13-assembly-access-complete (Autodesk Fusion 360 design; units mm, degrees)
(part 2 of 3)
sketch "B Facet 180 Triangle 3" plane through (0, -75, 0) normal (0, -1, 0) x axis (-1, 0, 0)
  line L1 (60.9665, 27.066) -> (-2.067, -27.066)
  line L2 (124, -27.066) -> (60.9665, 27.066)
  line L3 (-2.067, -27.066) -> (124, -27.066)
  line L4 (60.9665, 21.7934) -> (8.7304, -23.066)
  line L5 (113.2026, -23.066) -> (60.9665, 21.7934)
  line L6 (8.7304, -23.066) -> (113.2026, -23.066)
  point P1 (0, 0)
  point P2 (-2.067, -27.066)
  point P3 (60.9665, 27.066)
  point P4 (124, -27.066)
  dimension "d477" distance P1 P2 = 2.067 (= "Linear Dimension-2")
  dimension "d478" distance P1 P2 = 27.066 (= "Linear Dimension-3")
  dimension "d479" distance P1 P3 = 60.9665 (= "Linear Dimension-4")
  dimension "d480" distance P1 P3 = 27.066 (= "Linear Dimension-5")
  dimension "d481" distance P1 P4 = 124 (= "Linear Dimension-6")
  dimension "d482" distance P1 P4 = 27.066 (= "Linear Dimension-7")
  dimension "d483" = 4 (= "memberWidth / 2")
extrude "Extrude14" cut sketch "B Facet 180 Triangle 3" profile of L5 L6 L4 against normal blind 4.7 (magnitude of "-( wall + 0.2 mm )")
sketch "B Facet 180 Triangle 4" plane through (0, -75, 0) normal (0, -1, 0) x axis (-1, 0, 0)
  line L1 (124, -27.066) -> (60.9665, 27.066)
  line L2 (124, 27.066) -> (124, -27.066)
  line L3 (60.9665, 27.066) -> (124, 27.066)
  line L4 (120, -18.3583) -> (71.7639, 23.066)
  line L5 (120, 23.066) -> (120, -18.3583)
  line L6 (71.7639, 23.066) -> (120, 23.066)
  point P1 (0, 0)
  point P2 (60.9665, 27.066)
  point P3 (124, -27.066)
  point P4 (124, 27.066)
  dimension "d486" distance P1 P2 = 60.9665 (= "Linear Dimension-2")
  dimension "d487" distance P1 P2 = 27.066 (= "Linear Dimension-3")
  dimension "d488" distance P1 P3 = 124 (= "Linear Dimension-4")
  dimension "d489" distance P1 P3 = 27.066 (= "Linear Dimension-5")
  dimension "d490" distance P1 P4 = 124 (= "Linear Dimension-6")
  dimension "d491" distance P1 P4 = 27.066 (= "Linear Dimension-7")
  dimension "d492" = -4 (= "-memberWidth / 2")
extrude "Extrude15" cut sketch "B Facet 180 Triangle 4" profile of L5 L6 L4 against normal blind 4.7 (magnitude of "-( wall + 0.2 mm )")
fillet "Fillet5" radius 1.5 (= "apertureRadius")
work_plane "WorkPlane11" RotateAngle 135 ExtraOffset 0
work_plane "WorkPlane12" AlongDistance 75 (= "bodyWidth / 2") ExtraOffset 0
sketch "B Facet 225 Triangle 1" plane through (0, -53.033, -53.033) normal (0, -0.7071, -0.7071) x axis (1, 0, 0)
  line L1 (23.9949, -27.066) -> (62.2721, 27.066)
  line L2 (0.1814, 27.066) -> (23.9949, -27.066)
  line L3 (62.2721, 27.066) -> (0.1814, 27.066)
  line L4 (24.81, -18.9852) -> (54.5447, 23.066)
  line L5 (6.311, 23.066) -> (24.81, -18.9852)
  line L6 (54.5447, 23.066) -> (6.311, 23.066)
  point P1 (0, 0)
  point P2 (62.2721, 27.066)
  point P3 (23.9949, -27.066)
  point P4 (0.1814, 27.066)
  dimension "d501" distance P1 P2 = 62.2721 (= "Linear Dimension-2")
  dimension "d502" distance P1 P2 = 27.066 (= "Linear Dimension-3")
  dimension "d503" distance P1 P3 = 23.9949 (= "Linear Dimension-4")
  dimension "d504" distance P1 P3 = 27.066 (= "Linear Dimension-5")
  dimension "d505" distance P1 P4 = 0.1814 (= "Linear Dimension-6")
  dimension "d506" distance P1 P4 = 27.066 (= "Linear Dimension-7")
  dimension "d507" = 4 (= "memberWidth / 2")
extrude "Extrude16" cut sketch "B Facet 225 Triangle 1" profile of L5 L6 L4 against normal blind 4.7 (magnitude of "-( wall + 0.2 mm )")
sketch "B Facet 225 Triangle 2" plane through (0, -53.033, -53.033) normal (0, -0.7071, -0.7071) x axis (1, 0, 0)
  line L1 (0.1814, 27.066) -> (23.9949, -27.066)
  line L2 (-74.6684, -27.066) -> (0.1814, 27.066)
  line L3 (23.9949, -27.066) -> (-74.6684, -27.066)
  line L4 (-1.4863, 20.9235) -> (17.8653, -23.066)
  line L5 (-62.3117, -23.066) -> (-1.4863, 20.9235)
  line L6 (17.8653, -23.066) -> (-62.3117, -23.066)
  point P1 (0, 0)
  point P2 (23.9949, -27.066)
  point P3 (0.1814, 27.066)
  point P4 (-74.6684, -27.066)
  dimension "d510" distance P1 P2 = 23.9949 (= "Linear Dimension-2")
  dimension "d511" distance P1 P2 = 27.066 (= "Linear Dimension-3")
  dimension "d512" distance P1 P3 = 0.1814 (= "Linear Dimension-4")
  dimension "d513" distance P1 P3 = 27.066 (= "Linear Dimension-5")
  dimension "d514" distance P1 P4 = 74.6684 (= "Linear Dimension-6")
  dimension "d515" distance P1 P4 = 27.066 (= "Linear Dimension-7")
  dimension "d516" = -4 (= "-memberWidth / 2")
extrude "Extrude17" cut sketch "B Facet 225 Triangle 2" profile of L5 L6 L4 against normal blind 4.7 (magnitude of "-( wall + 0.2 mm )")
sketch "B Facet 225 Triangle 3" plane through (0, -53.033, -53.033) normal (0, -0.7071, -0.7071) x axis (1, 0, 0)
  line L1 (-74.6684, -27.066) -> (0.1814, 27.066)
  line L2 (-124, 27.066) -> (-74.6684, -27.066)
  line L3 (0.1814, 27.066) -> (-124, 27.066)
  line L4 (-74.1179, -21.7315) -> (-12.1753, 23.066)
  line L5 (-114.9429, 23.066) -> (-74.1179, -21.7315)
  line L6 (-12.1753, 23.066) -> (-114.9429, 23.066)
  point P1 (0, 0)
  point P2 (0.1814, 27.066)
  point P3 (-74.6684, -27.066)
  point P4 (-124, 27.066)
  dimension "d519" distance P1 P2 = 0.1814 (= "Linear Dimension-2")
  dimension "d520" distance P1 P2 = 27.066 (= "Linear Dimension-3")
  dimension "d521" distance P1 P3 = 74.6684 (= "Linear Dimension-4")
  dimension "d522" distance P1 P3 = 27.066 (= "Linear Dimension-5")
  dimension "d523" distance P1 P4 = 124 (= "Linear Dimension-6")
  dimension "d524" distance P1 P4 = 27.066 (= "Linear Dimension-7")
  dimension "d525" = 4 (= "memberWidth / 2")
extrude "Extrude18" cut sketch "B Facet 225 Triangle 3" profile of L5 L6 L4 against normal blind 4.7 (magnitude of "-( wall + 0.2 mm )")
sketch "B Facet 225 Triangle 4" plane through (0, -53.033, -53.033) normal (0, -0.7071, -0.7071) x axis (1, 0, 0)
  line L1 (-124, 27.066) -> (-74.6684, -27.066)
  line L2 (-124, -27.066) -> (-124, 27.066)
  line L3 (-74.6684, -27.066) -> (-124, -27.066)
  line L4 (-120, 16.7383) -> (-83.7255, -23.066)
  line L5 (-120, -23.066) -> (-120, 16.7383)
  line L6 (-83.7255, -23.066) -> (-120, -23.066)
  point P1 (0, 0)
  point P2 (-74.6684, -27.066)
  point P3 (-124, 27.066)
  point P4 (-124, -27.066)
  dimension "d528" distance P1 P2 = 74.6684 (= "Linear Dimension-2")
  dimension "d529" distance P1 P2 = 27.066 (= "Linear Dimension-3")
  dimension "d530" distance P1 P3 = 124 (= "Linear Dimension-4")
  dimension "d531" distance P1 P3 = 27.066 (= "Linear Dimension-5")
  dimension "d532" distance P1 P4 = 124 (= "Linear Dimension-6")
  dimension "d533" distance P1 P4 = 27.066 (= "Linear Dimension-7")
  dimension "d534" = -4 (= "-memberWidth / 2")
extrude "Extrude19" cut sketch "B Facet 225 Triangle 4" profile of L5 L6 L4 against normal blind 4.7 (magnitude of "-( wall + 0.2 mm )")
fillet "Fillet6" radius 1.5 (= "apertureRadius")
work_plane "WorkPlane13" RotateAngle 180 ExtraOffset 0
work_plane "WorkPlane14" AlongDistance 75 (= "bodyWidth / 2") ExtraOffset 0
sketch "B Facet 270 Triangle 1" plane through (0, 0, -75) normal (0, 0, -1) x axis (-1, 0, 0)
  line L1 (36.9655, 27.066) -> (-17.1665, -27.066)
  line L2 (53.4167, -27.066) -> (36.9655, 27.066)
  line L3 (-17.1665, -27.066) -> (53.4167, -27.066)
  line L4 (35.0777, 19.5214) -> (-7.5097, -23.066)
  line L5 (48.0205, -23.066) -> (35.0777, 19.5214)
  line L6 (-7.5097, -23.066) -> (48.0205, -23.066)
  point P1 (0, 0)
  point P2 (-17.1665, -27.066)
  point P3 (36.9655, 27.066)
  point P4 (53.4167, -27.066)
  dimension "d543" distance P1 P2 = 17.1665 (= "Linear Dimension-2")
  dimension "d544" distance P1 P2 = 27.066 (= "Linear Dimension-3")
  dimension "d545" distance P1 P3 = 36.9655 (= "Linear Dimension-4")
  dimension "d546" distance P1 P3 = 27.066 (= "Linear Dimension-5")
  dimension "d547" distance P1 P4 = 53.4167 (= "Linear Dimension-6")
  dimension "d548" distance P1 P4 = 27.066 (= "Linear Dimension-7")
  dimension "d549" = 4 (= "memberWidth / 2")
extrude "Extrude20" cut sketch "B Facet 270 Triangle 1" profile of L5 L6 L4 against normal blind 4.7 (magnitude of "-( wall + 0.2 mm )")
sketch "B Facet 270 Triangle 2" plane through (0, 0, -75) normal (0, 0, -1) x axis (-1, 0, 0)
  line L1 (53.4167, -27.066) -> (36.9655, 27.066)
  line L2 (124, 27.066) -> (53.4167, -27.066)
  line L3 (36.9655, 27.066) -> (124, 27.066)
  line L4 (55.5648, -20.3777) -> (42.3618, 23.066)
  line L5 (112.2115, 23.066) -> (55.5648, -20.3777)
  line L6 (42.3618, 23.066) -> (112.2115, 23.066)
  point P1 (0, 0)
  point P2 (36.9655, 27.066)
  point P3 (53.4167, -27.066)
  point P4 (124, 27.066)
  dimension "d552" distance P1 P2 = 36.9655 (= "Linear Dimension-2")
  dimension "d553" distance P1 P2 = 27.066 (= "Linear Dimension-3")
  dimension "d554" distance P1 P3 = 53.4167 (= "Linear Dimension-4")
  dimension "d555" distance P1 P3 = 27.066 (= "Linear Dimension-5")
  dimension "d556" distance P1 P4 = 124 (= "Linear Dimension-6")
  dimension "d557" distance P1 P4 = 27.066 (= "Linear Dimension-7")
  dimension "d558" = -4 (= "-memberWidth / 2")
extrude "Extrude21" cut sketch "B Facet 270 Triangle 2" profile of L5 L6 L4 against normal blind 4.7 (magnitude of "-( wall + 0.2 mm )")
sketch "B Facet 270 Triangle 3" plane through (0, 0, -75) normal (0, 0, -1) x axis (-1, 0, 0)
  line L1 (124, 27.066) -> (53.4167, -27.066)
  line L2 (124, -27.066) -> (124, 27.066)
  line L3 (53.4167, -27.066) -> (124, -27.066)
  line L4 (120, 18.9574) -> (65.2053, -23.066)
  line L5 (120, -23.066) -> (120, 18.9574)
  line L6 (65.2053, -23.066) -> (120, -23.066)
  point P1 (0, 0)
  point P2 (53.4167, -27.066)
  point P3 (124, 27.066)
  point P4 (124, -27.066)
  dimension "d561" distance P1 P2 = 53.4167 (= "Linear Dimension-2")
  dimension "d562" distance P1 P2 = 27.066 (= "Linear Dimension-3")
  dimension "d563" distance P1 P3 = 124 (= "Linear Dimension-4")
  dimension "d564" distance P1 P3 = 27.066 (= "Linear Dimension-5")
  dimension "d565" distance P1 P4 = 124 (= "Linear Dimension-6")
  dimension "d566" distance P1 P4 = 27.066 (= "Linear Dimension-7")
  dimension "d567" = 4 (= "memberWidth / 2")
extrude "Extrude22" cut sketch "B Facet 270 Triangle 3" profile of L5 L6 L4 against normal blind 4.7 (magnitude of "-( wall + 0.2 mm )")
fillet "Fillet7" radius 1.5 (= "apertureRadius")
work_plane "WorkPlane15" RotateAngle 225 ExtraOffset 0
work_plane "WorkPlane16" AlongDistance 75 (= "bodyWidth / 2") ExtraOffset 0
sketch "B Facet 315 Triangle 1" plane through (0, 53.033, -53.033) normal (0, 0.7071, -0.7071) x axis (1, 0, 0)
  line L1 (-82.0711, -27.066) -> (-43.7939, 27.066)
  line L2 (-124, 27.066) -> (-82.0711, -27.066)
  line L3 (-43.7939, 27.066) -> (-124, 27.066)
  line L4 (-82.2175, -20.3449) -> (-51.5213, 23.066)
  line L5 (-115.8422, 23.066) -> (-82.2175, -20.3449)
  line L6 (-51.5213, 23.066) -> (-115.8422, 23.066)
  point P1 (0, 0)
  point P2 (-43.7939, 27.066)
  point P3 (-82.0711, -27.066)
  point P4 (-124, 27.066)
  dimension "d576" distance P1 P2 = 43.7939 (= "Linear Dimension-2")
  dimension "d577" distance P1 P2 = 27.066 (= "Linear Dimension-3")
  dimension "d578" distance P1 P3 = 82.0711 (= "Linear Dimension-4")
  dimension "d579" distance P1 P3 = 27.066 (= "Linear Dimension-5")
  dimension "d580" distance P1 P4 = 124 (= "Linear Dimension-6")
  dimension "d581" distance P1 P4 = 27.066 (= "Linear Dimension-7")
  dimension "d582" = 4 (= "memberWidth / 2")
extrude "Extrude23" cut sketch "B Facet 315 Triangle 1" profile of L5 L6 L4 against normal blind 4.7 (magnitude of "-( wall + 0.2 mm )")
sketch "B Facet 315 Triangle 2" plane through (0, 53.033, -53.033) normal (0, 0.7071, -0.7071) x axis (1, 0, 0)
  line L1 (-124, 27.066) -> (-82.0711, -27.066)
  line L2 (-124, -27.066) -> (-124, 27.066)
  line L3 (-82.0711, -27.066) -> (-124, -27.066)
  line L4 (-120, 15.3697) -> (-90.2289, -23.066)
  line L5 (-120, -23.066) -> (-120, 15.3697)
  line L6 (-90.2289, -23.066) -> (-120, -23.066)
  point P1 (0, 0)
  point P2 (-82.0711, -27.066)
  point P3 (-124, 27.066)
  point P4 (-124, -27.066)
  dimension "d585" distance P1 P2 = 82.0711 (= "Linear Dimension-2")
  dimension "d586" distance P1 P2 = 27.066 (= "Linear Dimension-3")
  dimension "d587" distance P1 P3 = 124 (= "Linear Dimension-4")
  dimension "d588" distance P1 P3 = 27.066 (= "Linear Dimension-5")
  dimension "d589" distance P1 P4 = 124 (= "Linear Dimension-6")
  dimension "d590" distance P1 P4 = 27.066 (= "Linear Dimension-7")
  dimension "d591" = -4 (= "-memberWidth / 2")
extrude "Extrude24" cut sketch "B Facet 315 Triangle 2" profile of L5 L6 L4 against normal blind 4.7 (magnitude of "-( wall + 0.2 mm )")
fillet "Fillet8" radius 1.5 (= "apertureRadius")
work_plane "WorkPlane17" AlongDistance 0.5 (= "qFront") ExtraOffset 0
sketch "A Central Carrier sketch" plane through (0.3536, 0.3536, 0) normal (0.7071, 0.7071, 0) x axis (0, 0, 1)
  circle C1 centre (0, 0) radius 26
  dimension "d598" diameter C1 = 52 (= "carrierOD")
extrude "Extrude25" new body sketch "A Central Carrier sketch" along normal blind 18 (= "spokeDepth")
work_plane "WorkPlane18" AlongDistance 0.5 (= "qFront") ExtraOffset 0
sketch "A Spoke 1 Profile" plane through (0.3536, 0.3536, 0) normal (0.7071, 0.7071, 0) x axis (0, 0, 1)
  line L1 (37.3643, -145.3579) -> (-4.7984, -1.4054)
  line L2 (46.9611, -142.547) -> (37.3643, -145.3579)
  line L3 (4.7984, 1.4054) -> (46.9611, -142.547)
  line L4 (-4.7984, -1.4054) -> (4.7984, 1.4054)
  point P1 (0, 0)
  point P2 (-4.7984, -1.4054)
  point P3 (37.3643, -145.3579)
  point P4 (46.9611, -142.547)
  point P5 (4.7984, 1.4054)
  dimension "d603" distance P1 P2 = 4.7984 (= "Linear Dimension-2")
  dimension "d604" distance P1 P2 = 1.4054 (= "Linear Dimension-3")
  dimension "d605" distance P1 P3 = 37.3643 (= "Linear Dimension-4")
  dimension "d606" distance P1 P3 = 145.3579 (= "Linear Dimension-5")
  dimension "d607" distance P1 P4 = 46.9611 (= "Linear Dimension-6")
  dimension "d608" distance P1 P4 = 142.547 (= "Linear Dimension-7")
  dimension "d609" distance P1 P5 = 4.7984 (= "Linear Dimension-8")
  dimension "d610" distance P1 P5 = 1.4054 (= "Linear Dimension-9")
extrude "Extrude26" add sketch "A Spoke 1 Profile" along normal blind 18 (= "spokeDepth")
sketch "A Spoke 2 Profile" plane through (0.3536, 0.3536, 0) normal (0.7071, 0.7071, 0) x axis (0, 0, 1)
  line L1 (126.9012, -80.1317) -> (-2.5272, -4.3143)
  line L2 (131.9557, -71.5031) -> (126.9012, -80.1317)
  line L3 (2.5272, 4.3143) -> (131.9557, -71.5031)
  line L4 (-2.5272, -4.3143) -> (2.5272, 4.3143)
  point P1 (0, 0)
  point P2 (-2.5272, -4.3143)
  point P3 (126.9012, -80.1317)
  point P4 (131.9557, -71.5031)
  point P5 (2.5272, 4.3143)
  dimension "d613" distance P1 P2 = 2.5272 (= "Linear Dimension-2")
  dimension "d614" distance P1 P2 = 4.3143 (= "Linear Dimension-3")
  dimension "d615" distance P1 P3 = 126.9012 (= "Linear Dimension-4")
  dimension "d616" distance P1 P3 = 80.1317 (= "Linear Dimension-5")
  dimension "d617" distance P1 P4 = 131.9557 (= "Linear Dimension-6")
  dimension "d618" distance P1 P4 = 71.5031 (= "Linear Dimension-7")
  dimension "d619" distance P1 P5 = 2.5272 (= "Linear Dimension-8")
  dimension "d620" distance P1 P5 = 4.3143 (= "Linear Dimension-9")
extrude "Extrude27" add sketch "A Spoke 2 Profile" along normal blind 18 (= "spokeDepth")
sketch "A Spoke 3 Profile" plane through (0.3536, 0.3536, 0) normal (0.7071, 0.7071, 0) x axis (0, 0, 1)
  line L1 (131.9557, 71.5031) -> (2.5272, -4.3143)
  line L2 (126.9012, 80.1317) -> (131.9557, 71.5031)
  line L3 (-2.5272, 4.3143) -> (126.9012, 80.1317)
  line L4 (2.5272, -4.3143) -> (-2.5272, 4.3143)
  point P1 (0, 0)
  point P2 (2.5272, -4.3143)
  point P3 (131.9557, 71.5031)
  point P4 (126.9012, 80.1317)
  point P5 (-2.5272, 4.3143)
  dimension "d623" distance P1 P2 = 2.5272 (= "Linear Dimension-2")
  dimension "d624" distance P1 P2 = 4.3143 (= "Linear Dimension-3")
  dimension "d625" distance P1 P3 = 131.9557 (= "Linear Dimension-4")
  dimension "d626" distance P1 P3 = 71.5031 (= "Linear Dimension-5")
  dimension "d627" distance P1 P4 = 126.9012 (= "Linear Dimension-6")
  dimension "d628" distance P1 P4 = 80.1317 (= "Linear Dimension-7")
  dimension "d629" distance P1 P5 = 2.5272 (= "Linear Dimension-8")
  dimension "d630" distance P1 P5 = 4.3143 (= "Linear Dimension-9")
extrude "Extrude28" add sketch "A Spoke 3 Profile" along normal blind 18 (= "spokeDepth")
sketch "A Spoke 4 Profile" plane through (0.3536, 0.3536, 0) normal (0.7071, 0.7071, 0) x axis (0, 0, 1)
  line L1 (46.9611, 142.547) -> (4.7984, -1.4054)
  line L2 (37.3643, 145.3579) -> (46.9611, 142.547)
  line L3 (-4.7984, 1.4054) -> (37.3643, 145.3579)
  line L4 (4.7984, -1.4054) -> (-4.7984, 1.4054)
  point P1 (0, 0)
  point P2 (4.7984, -1.4054)
  point P3 (46.9611, 142.547)
  point P4 (37.3643, 145.3579)
  point P5 (-4.7984, 1.4054)
  dimension "d633" distance P1 P2 = 4.7984 (= "Linear Dimension-2")
  dimension "d634" distance P1 P2 = 1.4054 (= "Linear Dimension-3")
  dimension "d635" distance P1 P3 = 46.9611 (= "Linear Dimension-4")
  dimension "d636" distance P1 P3 = 142.547 (= "Linear Dimension-5")
  dimension "d637" distance P1 P4 = 37.3643 (= "Linear Dimension-6")
  dimension "d638" distance P1 P4 = 145.3579 (= "Linear Dimension-7")
  dimension "d639" distance P1 P5 = 4.7984 (= "Linear Dimension-8")
  dimension "d640" distance P1 P5 = 1.4054 (= "Linear Dimension-9")
extrude "Extrude29" add sketch "A Spoke 4 Profile" along normal blind 18 (= "spokeDepth")
sketch "A Spoke 5 Profile" plane through (0.3536, 0.3536, 0) normal (0.7071, 0.7071, 0) x axis (0, 0, 1)
  line L1 (-37.3643, 145.3579) -> (4.7984, 1.4054)
  line L2 (-46.9611, 142.547) -> (-37.3643, 145.3579)
  line L3 (-4.7984, -1.4054) -> (-46.9611, 142.547)
  line L4 (4.7984, 1.4054) -> (-4.7984, -1.4054)
  point P1 (0, 0)
  point P2 (4.7984, 1.4054)
  point P3 (-37.3643, 145.3579)
  point P4 (-46.9611, 142.547)
  point P5 (-4.7984, -1.4054)
  dimension "d643" distance P1 P2 = 4.7984 (= "Linear Dimension-2")
  dimension "d644" distance P1 P2 = 1.4054 (= "Linear Dimension-3")
  dimension "d645" distance P1 P3 = 37.3643 (= "Linear Dimension-4")
  dimension "d646" distance P1 P3 = 145.3579 (= "Linear Dimension-5")
  dimension "d647" distance P1 P4 = 46.9611 (= "Linear Dimension-6")
  dimension "d648" distance P1 P4 = 142.547 (= "Linear Dimension-7")
  dimension "d649" distance P1 P5 = 4.7984 (= "Linear Dimension-8")
  dimension "d650" distance P1 P5 = 1.4054 (= "Linear Dimension-9")
extrude "Extrude30" add sketch "A Spoke 5 Profile" along normal blind 18 (= "spokeDepth")
sketch "A Spoke 6 Profile" plane through (0.3536, 0.3536, 0) normal (0.7071, 0.7071, 0) x axis (0, 0, 1)
  line L1 (-126.9012, 80.1317) -> (2.5272, 4.3143)
  line L2 (-131.9557, 71.5031) -> (-126.9012, 80.1317)
  line L3 (-2.5272, -4.3143) -> (-131.9557, 71.5031)
  line L4 (2.5272, 4.3143) -> (-2.5272, -4.3143)
  point P1 (0, 0)
  point P2 (2.5272, 4.3143)
  point P3 (-126.9012, 80.1317)
  point P4 (-131.9557, 71.5031)
  point P5 (-2.5272, -4.3143)
  dimension "d653" distance P1 P2 = 2.5272 (= "Linear Dimension-2")
  dimension "d654" distance P1 P2 = 4.3143 (= "Linear Dimension-3")
  dimension "d655" distance P1 P3 = 126.9012 (= "Linear Dimension-4")
  dimension "d656" distance P1 P3 = 80.1317 (= "Linear Dimension-5")
  dimension "d657" distance P1 P4 = 131.9557 (= "Linear Dimension-6")
  dimension "d658" distance P1 P4 = 71.5031 (= "Linear Dimension-7")
  dimension "d659" distance P1 P5 = 2.5272 (= "Linear Dimension-8")
  dimension "d660" distance P1 P5 = 4.3143 (= "Linear Dimension-9")
extrude "Extrude31" add sketch "A Spoke 6 Profile" along normal blind 18 (= "spokeDepth")
sketch "A Spoke 7 Profile" plane through (0.3536, 0.3536, 0) normal (0.7071, 0.7071, 0) x axis (0, 0, 1)
  line L1 (-131.9557, -71.5031) -> (-2.5272, 4.3143)
  line L2 (-126.9012, -80.1317) -> (-131.9557, -71.5031)
  line L3 (2.5272, -4.3143) -> (-126.9012, -80.1317)
  line L4 (-2.5272, 4.3143) -> (2.5272, -4.3143)
  point P1 (0, 0)
  point P2 (-2.5272, 4.3143)
  point P3 (-131.9557, -71.5031)
  point P4 (-126.9012, -80.1317)
  point P5 (2.5272, -4.3143)
  dimension "d663" distance P1 P2 = 2.5272 (= "Linear Dimension-2")
  dimension "d664" distance P1 P2 = 4.3143 (= "Linear Dimension-3")
  dimension "d665" distance P1 P3 = 131.9557 (= "Linear Dimension-4")
  dimension "d666" distance P1 P3 = 71.5031 (= "Linear Dimension-5")
  dimension "d667" distance P1 P4 = 126.9012 (= "Linear Dimension-6")
  dimension "d668" distance P1 P4 = 80.1317 (= "Linear Dimension-7")
  dimension "d669" distance P1 P5 = 2.5272 (= "Linear Dimension-8")
  dimension "d670" distance P1 P5 = 4.3143 (= "Linear Dimension-9")
extrude "Extrude32" add sketch "A Spoke 7 Profile" along normal blind 18 (= "spokeDepth")
sketch "A Spoke 8 Profile" plane through (0.3536, 0.3536, 0) normal (0.7071, 0.7071, 0) x axis (0, 0, 1)
  line L1 (-46.9611, -142.547) -> (-4.7984, 1.4054)
  line L2 (-37.3643, -145.3579) -> (-46.9611, -142.547)
  line L3 (4.7984, 1.4054) -> (-37.3643, -145.3579)
  line L4 (-4.7984, 1.4054) -> (4.7984, 1.4054)
  point P1 (0, 0)
  point P2 (-4.7984, 1.4054)
  point P3 (-46.9611, -142.547)
  point P4 (-37.3643, -145.3579)
  point P5 (4.7984, 1.4054)
  dimension "d673" distance P1 P2 = 4.7984 (= "Linear Dimension-2")
  dimension "d674" distance P1 P2 = 1.4054 (= "Linear Dimension-3")
  dimension "d675" distance P1 P3 = 46.9611 (= "Linear Dimension-4")
  dimension "d676" distance P1 P3 = 142.547 (= "Linear Dimension-5")
  dimension "d677" distance P1 P4 = 37.3643 (= "Linear Dimension-6")
  dimension "d678" distance P1 P4 = 145.3579 (= "Linear Dimension-7")
  dimension "d679" distance P1 P5 = 4.7984 (= "Linear Dimension-8")
  dimension "d680" distance P1 P5 = 1.4054 (= "Linear Dimension-9")
extrude "Extrude33" add sketch "A Spoke 8 Profile" along normal blind 18 (= "spokeDepth")
sketch "Spoke Outer Envelope" plane through (0, 0, 0) normal (1, 0, 0) x axis (0, 0, -1)
  line L1 (31.066, 75) -> (75, 31.066)
  line L2 (-31.066, 75) -> (31.066, 75)
  line L3 (-75, 31.066) -> (-31.066, 75)
  line L4 (-75, -31.066) -> (-75, 31.066)
  line L5 (-31.066, -75) -> (-75, -31.066)
  line L6 (31.066, -75) -> (-31.066, -75)
  line L7 (75, -31.066) -> (31.066, -75)
  line L8 (75, 31.066) -> (75, -31.066)
  point P1 (0, 0)
  point P10 (0, 0)
  point P3 (31.066, 75)
  point P8 (31.066, -75)
  coincident P1 P10
  horizontal L2
  dimension "d683" distance P3 P8 = 150 (= "bodyWidth")
extrude "Extrude34" sketch "Spoke Outer Envelope" distance 260 (= "bodyLength")
fillet "Fillet9" radius 1 (= "rootRadius")
work_plane "WorkPlane19" AlongDistance 10.6 (= "qFrontBack") ExtraOffset 0
sketch "A Rear Carrier Clearance sketch" plane through (7.4953, 7.4953, 0) normal (0.7071, 0.7071, 0) x axis (0, 0, 1)
  circle C1 centre (0, 0) radius 23
  dimension "d690" diameter C1 = 46 (= "rearCarrierClearance")
extrude "Extrude35" cut sketch "A Rear Carrier Clearance sketch" along normal blind 18 (= "spokeDepth")
work_plane "WorkPlane20" AlongDistance 0.5 (= "qFront") ExtraOffset 0
sketch "A Seal Relief sketch" plane through (0.3536, 0.3536, 0) normal (0.7071, 0.7071, 0) x axis (0, 0, 1)
  circle C1 centre (0, 0) radius 9.75
  dimension "d695" diameter C1 = 19.5 (= "raceRelief")
extrude "Extrude36" cut sketch "A Seal Relief sketch" along normal blind 10.1 (= "frontSeatDepth + shoulder")
work_plane "WorkPlane21" AlongDistance 0.5 (= "qFront") ExtraOffset 0
sketch "A Front Bearing Seat sketch" plane through (0.3536, 0.3536, 0) normal (0.7071, 0.7071, 0) x axis (0, 0, 1)
  circle C1 centre (0, 0) radius 11.1
  dimension "d700" diameter C1 = 22.2 (= "seatDiameter")
extrude "Extrude37" cut sketch "A Front Bearing Seat sketch" along normal blind 7.1 (= "frontSeatDepth")
work_plane "WorkPlane22" AlongDistance 0.5 (= "qFront") ExtraOffset 0
sketch "A Support Bolt seed" plane through (0.3536, 0.3536, 0) normal (0.7071, 0.7071, 0) x axis (0, 0, 1)
  line L1 (17, 0) -> (0, 0)
  circle C1 centre (17, 0) radius 1.65
  point P1 (0, 0)
  point P2 (17, 0)
  horizontal L1
  dimension "d705" distance P1 P2 = 17 (= "supportCircle / 2")
  dimension "d706" diameter C1 = 3.3 (= "m3Clearance")
extrude "Extrude38" cut sketch "A Support Bolt seed" profile of C1 along normal blind 10.1 (= "frontSeatDepth + shoulder")
circular_pattern "C-Pattern1" TotalAngle 360
work_plane "WorkPlane23" AlongDistance 0.5 (= "qFront") ExtraOffset 0
sketch "A Front Bearing Boss sketch" plane through (0.3536, 0.3536, 0) normal (0.7071, 0.7071, 0) x axis (0, 0, 1)
  circle C1 centre (0, 0) radius 22
  dimension "d713" diameter C1 = 44 (= "coreOD")
chamfer "Chamfer1" distance 0.4 (= "entryChamfer")
work_plane "WorkPlane24" AlongDistance 75 (= "bodyWidth / 2") ExtraOffset 0
sketch "A Collar Driver Corridors" plane through (0, 0, 75) normal (0, 0, 1) x axis (1, 0, 0)
  circle C1 centre (6.7175, 15.9099) radius 3
  circle C2 centre (15.9099, 6.7175) radius 3
  point P1 (0, 0)
  point P2 (6.7175, 15.9099)
  point P3 (15.9099, 6.7175)
  dimension "d717" distance P1 P2 = 6.7175 (= "abs(( 16 mm + ( -6.5 mm ) ) / sqrt(2))")
  dimension "d718" distance P1 P2 = 15.9099 (= "abs(( 16 mm - ( -6.5 mm ) ) / sqrt(2))")
  dimension "d719" diameter C1 = 6
  dimension "d720" distance P1 P3 = 15.9099 (= "abs(( 16 mm + ( 6.5 mm ) ) / sqrt(2))")
  dimension "d721" distance P1 P3 = 6.7175 (= "abs(( 16 mm - ( 6.5 mm ) ) / sqrt(2))")
  dimension "d722" diameter C2 = 6
extrude "Extrude39" cut sketch "A Collar Driver Corridors" against normal blind 75 (magnitude of "-( bodyWidth / 2 )")
work_plane "WorkPlane17" ExtraOffset 0
sketch "B Central Carrier sketch" plane through (-0.3536, -0.3536, 0) normal (0.7071, 0.7071, 0) x axis (0, 0, 1)
  circle C1 centre (0, 0) radius 38
  dimension "d727" diameter C1 = 76 (= "mountOD")
extrude "Extrude25" new body sketch "B Central Carrier sketch" no distance stored
work_plane "WorkPlane18" ExtraOffset 0
sketch "B Spoke 1 Profile" plane through (-0.3536, -0.3536, 0) normal (0.7071, 0.7071, 0) x axis (0, 0, 1)
  line L1 (37.3643, -145.3579) -> (-4.7984, -1.4054)
  line L2 (46.9611, -142.547) -> (37.3643, -145.3579)
  line L3 (4.7984, 1.4054) -> (46.9611, -142.547)
  line L4 (-4.7984, -1.4054) -> (4.7984, 1.4054)
  point P1 (0, 0)
  point P2 (-4.7984, -1.4054)
  point P3 (37.3643, -145.3579)
  point P4 (46.9611, -142.547)
  point P5 (4.7984, 1.4054)
  dimension "d732" distance P1 P2 = 4.7984 (= "Linear Dimension-2")
  dimension "d733" distance P1 P2 = 1.4054 (= "Linear Dimension-3")
  dimension "d734" distance P1 P3 = 37.3643 (= "Linear Dimension-4")
  dimension "d735" distance P1 P3 = 145.3579 (= "Linear Dimension-5")
  dimension "d736" distance P1 P4 = 46.9611 (= "Linear Dimension-6")
  dimension "d737" distance P1 P4 = 142.547 (= "Linear Dimension-7")
  dimension "d738" distance P1 P5 = 4.7984 (= "Linear Dimension-8")
  dimension "d739" distance P1 P5 = 1.4054 (= "Linear Dimension-9")
extrude "Extrude26" add sketch "B Spoke 1 Profile" no distance stored
sketch "B Spoke 2 Profile" plane through (-0.3536, -0.3536, 0) normal (0.7071, 0.7071, 0) x axis (0, 0, 1)
  line L1 (126.9012, -80.1317) -> (-2.5272, -4.3143)
  line L2 (131.9557, -71.5031) -> (126.9012, -80.1317)
  line L3 (2.5272, 4.3143) -> (131.9557, -71.5031)
  line L4 (-2.5272, -4.3143) -> (2.5272, 4.3143)
  point P1 (0, 0)
  point P2 (-2.5272, -4.3143)
  point P3 (126.9012, -80.1317)
  point P4 (131.9557, -71.5031)
  point P5 (2.5272, 4.3143)
  dimension "d742" distance P1 P2 = 2.5272 (= "Linear Dimension-2")
  dimension "d743" distance P1 P2 = 4.3143 (= "Linear Dimension-3")
  dimension "d744" distance P1 P3 = 126.9012 (= "Linear Dimension-4")
  dimension "d745" distance P1 P3 = 80.1317 (= "Linear Dimension-5")
  dimension "d746" distance P1 P4 = 131.9557 (= "Linear Dimension-6")
  dimension "d747" distance P1 P4 = 71.5031 (= "Linear Dimension-7")
  dimension "d748" distance P1 P5 = 2.5272 (= "Linear Dimension-8")
  dimension "d749" distance P1 P5 = 4.3143 (= "Linear Dimension-9")
extrude "Extrude27" add sketch "B Spoke 2 Profile" no distance stored
sketch "B Spoke 3 Profile" plane through (-0.3536, -0.3536, 0) normal (0.7071, 0.7071, 0) x axis (0, 0, 1)
  line L1 (131.9557, 71.5031) -> (2.5272, -4.3143)
  line L2 (126.9012, 80.1317) -> (131.9557, 71.5031)
  line L3 (-2.5272, 4.3143) -> (126.9012, 80.1317)
  line L4 (2.5272, -4.3143) -> (-2.5272, 4.3143)
  point P1 (0, 0)
  point P2 (2.5272, -4.3143)
  point P3 (131.9557, 71.5031)
  point P4 (126.9012, 80.1317)
  point P5 (-2.5272, 4.3143)
  dimension "d752" distance P1 P2 = 2.5272 (= "Linear Dimension-2")
  dimension "d753" distance P1 P2 = 4.3143 (= "Linear Dimension-3")
  dimension "d754" distance P1 P3 = 131.9557 (= "Linear Dimension-4")
  dimension "d755" distance P1 P3 = 71.5031 (= "Linear Dimension-5")
  dimension "d756" distance P1 P4 = 126.9012 (= "Linear Dimension-6")
  dimension "d757" distance P1 P4 = 80.1317 (= "Linear Dimension-7")
  dimension "d758" distance P1 P5 = 2.5272 (= "Linear Dimension-8")
  dimension "d759" distance P1 P5 = 4.3143 (= "Linear Dimension-9")
extrude "Extrude28" add sketch "B Spoke 3 Profile" no distance stored
sketch "B Spoke 4 Profile" plane through (-0.3536, -0.3536, 0) normal (0.7071, 0.7071, 0) x axis (0, 0, 1)
  line L1 (46.9611, 142.547) -> (4.7984, -1.4054)
  line L2 (37.3643, 145.3579) -> (46.9611, 142.547)
  line L3 (-4.7984, 1.4054) -> (37.3643, 145.3579)
  line L4 (4.7984, -1.4054) -> (-4.7984, 1.4054)
  point P1 (0, 0)
  point P2 (4.7984, -1.4054)
  point P3 (46.9611, 142.547)
  point P4 (37.3643, 145.3579)
  point P5 (-4.7984, 1.4054)
  dimension "d762" distance P1 P2 = 4.7984 (= "Linear Dimension-2")
  dimension "d763" distance P1 P2 = 1.4054 (= "Linear Dimension-3")
  dimension "d764" distance P1 P3 = 46.9611 (= "Linear Dimension-4")
  dimension "d765" distance P1 P3 = 142.547 (= "Linear Dimension-5")
  dimension "d766" distance P1 P4 = 37.3643 (= "Linear Dimension-6")
  dimension "d767" distance P1 P4 = 145.3579 (= "Linear Dimension-7")
  dimension "d768" distance P1 P5 = 4.7984 (= "Linear Dimension-8")
  dimension "d769" distance P1 P5 = 1.4054 (= "Linear Dimension-9")
extrude "Extrude29" add sketch "B Spoke 4 Profile" no distance stored
sketch "B Spoke 5 Profile" plane through (-0.3536, -0.3536, 0) normal (0.7071, 0.7071, 0) x axis (0, 0, 1)
  line L1 (-37.3643, 145.3579) -> (4.7984, 1.4054)
  line L2 (-46.9611, 142.547) -> (-37.3643, 145.3579)
  line L3 (-4.7984, -1.4054) -> (-46.9611, 142.547)
  line L4 (4.7984, 1.4054) -> (-4.7984, -1.4054)
  point P1 (0, 0)
  point P2 (4.7984, 1.4054)
  point P3 (-37.3643, 145.3579)
  point P4 (-46.9611, 142.547)
  point P5 (-4.7984, -1.4054)
  dimension "d772" distance P1 P2 = 4.7984 (= "Linear Dimension-2")
  dimension "d773" distance P1 P2 = 1.4054 (= "Linear Dimension-3")
  dimension "d774" distance P1 P3 = 37.3643 (= "Linear Dimension-4")
  dimension "d775" distance P1 P3 = 145.3579 (= "Linear Dimension-5")
  dimension "d776" distance P1 P4 = 46.9611 (= "Linear Dimension-6")
  dimension "d777" distance P1 P4 = 142.547 (= "Linear Dimension-7")
  dimension "d778" distance P1 P5 = 4.7984 (= "Linear Dimension-8")
  dimension "d779" distance P1 P5 = 1.4054 (= "Linear Dimension-9")
extrude "Extrude30" add sketch "B Spoke 5 Profile" no distance stored
sketch "B Spoke 6 Profile" plane through (-0.3536, -0.3536, 0) normal (0.7071, 0.7071, 0) x axis (0, 0, 1)
  line L1 (-126.9012, 80.1317) -> (2.5272, 4.3143)
  line L2 (-131.9557, 71.5031) -> (-126.9012, 80.1317)
  line L3 (-2.5272, -4.3143) -> (-131.9557, 71.5031)
  line L4 (2.5272, 4.3143) -> (-2.5272, -4.3143)
  point P1 (0, 0)
  point P2 (2.5272, 4.3143)
  point P3 (-126.9012, 80.1317)
  point P4 (-131.9557, 71.5031)
  point P5 (-2.5272, -4.3143)
  dimension "d782" distance P1 P2 = 2.5272 (= "Linear Dimension-2")
  dimension "d783" distance P1 P2 = 4.3143 (= "Linear Dimension-3")
  dimension "d784" distance P1 P3 = 126.9012 (= "Linear Dimension-4")
  dimension "d785" distance P1 P3 = 80.1317 (= "Linear Dimension-5")
  dimension "d786" distance P1 P4 = 131.9557 (= "Linear Dimension-6")
  dimension "d787" distance P1 P4 = 71.5031 (= "Linear Dimension-7")
  dimension "d788" distance P1 P5 = 2.5272 (= "Linear Dimension-8")
  dimension "d789" distance P1 P5 = 4.3143 (= "Linear Dimension-9")
extrude "Extrude31" add sketch "B Spoke 6 Profile" no distance stored
sketch "B Spoke 7 Profile" plane through (-0.3536, -0.3536, 0) normal (0.7071, 0.7071, 0) x axis (0, 0, 1)
  line L1 (-131.9557, -71.5031) -> (-2.5272, 4.3143)
  line L2 (-126.9012, -80.1317) -> (-131.9557, -71.5031)
  line L3 (2.5272, -4.3143) -> (-126.9012, -80.1317)
  line L4 (-2.5272, 4.3143) -> (2.5272, -4.3143)
  point P1 (0, 0)
  point P2 (-2.5272, 4.3143)
  point P3 (-131.9557, -71.5031)
  point P4 (-126.9012, -80.1317)
  point P5 (2.5272, -4.3143)
  dimension "d792" distance P1 P2 = 2.5272 (= "Linear Dimension-2")
  dimension "d793" distance P1 P2 = 4.3143 (= "Linear Dimension-3")
  dimension "d794" distance P1 P3 = 131.9557 (= "Linear Dimension-4")
  dimension "d795" distance P1 P3 = 71.5031 (= "Linear Dimension-5")
  dimension "d796" distance P1 P4 = 126.9012 (= "Linear Dimension-6")
  dimension "d797" distance P1 P4 = 80.1317 (= "Linear Dimension-7")
  dimension "d798" distance P1 P5 = 2.5272 (= "Linear Dimension-8")
  dimension "d799" distance P1 P5 = 4.3143 (= "Linear Dimension-9")
extrude "Extrude32" add sketch "B Spoke 7 Profile" no distance stored
sketch "B Spoke 8 Profile" plane through (-0.3536, -0.3536, 0) normal (0.7071, 0.7071, 0) x axis (0, 0, 1)
  line L1 (-46.9611, -142.547) -> (-4.7984, 1.4054)
  line L2 (-37.3643, -145.3579) -> (-46.9611, -142.547)
  line L3 (4.7984, 1.4054) -> (-37.3643, -145.3579)
  line L4 (-4.7984, 1.4054) -> (4.7984, 1.4054)
  point P1 (0, 0)
  point P2 (-4.7984, 1.4054)
  point P3 (-46.9611, -142.547)
  point P4 (-37.3643, -145.3579)
  point P5 (4.7984, 1.4054)
  dimension "d802" distance P1 P2 = 4.7984 (= "Linear Dimension-2")
  dimension "d803" distance P1 P2 = 1.4054 (= "Linear Dimension-3")
  dimension "d804" distance P1 P3 = 46.9611 (= "Linear Dimension-4")
  dimension "d805" distance P1 P3 = 142.547 (= "Linear Dimension-5")
  dimension "d806" distance P1 P4 = 37.3643 (= "Linear Dimension-6")
  dimension "d807" distance P1 P4 = 145.3579 (= "Linear Dimension-7")
  dimension "d808" distance P1 P5 = 4.7984 (= "Linear Dimension-8")
  dimension "d809" distance P1 P5 = 1.4054 (= "Linear Dimension-9")
extrude "Extrude33" add sketch "B Spoke 8 Profile" no distance stored
sketch "Spoke Outer Envelope" plane through (0, 0, 0) normal (1, 0, 0) x axis (0, 0, -1)
  line L1 (31.066, 75) -> (75, 31.066)
  line L2 (-31.066, 75) -> (31.066, 75)
  line L3 (-75, 31.066) -> (-31.066, 75)
  line L4 (-75, -31.066) -> (-75, 31.066)
  line L5 (-31.066, -75) -> (-75, -31.066)
  line L6 (31.066, -75) -> (-31.066, -75)
  line L7 (75, -31.066) -> (31.066, -75)
  line L8 (75, 31.066) -> (75, -31.066)
  point P1 (0, 0)
  point P10 (0, 0)
  point P3 (31.066, 75)
  point P8 (31.066, -75)
  coincident P1 P10
  horizontal L2
  dimension "d812" distance P3 P8 = 150 (= "bodyWidth")
extrude "Extrude34" sketch "Spoke Outer Envelope" distance 260 (= "bodyLength")
fillet "Fillet9" radius 1 (= "rootRadius")
work_plane "WorkPlane19" ExtraOffset 0
sketch "B Open Hub Cavity sketch" plane through (-0.3536, -0.3536, 0) normal (0.7071, 0.7071, 0) x axis (0, 0, 1)
  circle C1 centre (0, 0) radius 25.15
  dimension "d819" diameter C1 = 50.3 (= "mountOpening")
extrude "Extrude35" cut sketch "B Open Hub Cavity sketch" no distance stored
work_plane "WorkPlane20" ExtraOffset 0
sketch "B Four Mount Holes" plane through (-0.3536, -0.3536, 0) normal (0.7071, 0.7071, 0) x axis (0, 0, 1)
  circle C1 centre (22.6274, 22.6274) radius 2.15
  circle C2 centre (-22.6274, 22.6274) radius 2.15
  circle C3 centre (-22.6274, -22.6274) radius 2.15
  circle C4 centre (22.6274, -22.6274) radius 2.15
  point P1 (0, 0)
  point P2 (22.6274, 22.6274)
  point P3 (-22.6274, 22.6274)
  point P4 (-22.6274, -22.6274)
  point P5 (22.6274, -22.6274)
  dimension "d824" distance P1 P2 = 22.6274 (= "abs(mountCircle / ( 2 * sqrt(2) ))")
  dimension "d825" distance P1 P2 = 22.6274 (= "abs(mountCircle / ( 2 * sqrt(2) ))")
  dimension "d826" diameter C1 = 4.3 (= "m4Clearance")
  dimension "d827" distance P1 P3 = 22.6274 (= "abs(-mountCircle / ( 2 * sqrt(2) ))")
  dimension "d828" distance P1 P3 = 22.6274 (= "abs(mountCircle / ( 2 * sqrt(2) ))")
  dimension "d829" diameter C2 = 4.3 (= "m4Clearance")
  dimension "d830" distance P1 P4 = 22.6274 (= "abs(-mountCircle / ( 2 * sqrt(2) ))")
  dimension "d831" distance P1 P4 = 22.6274 (= "abs(-mountCircle / ( 2 * sqrt(2) ))")
  dimension "d832" diameter C3 = 4.3 (= "m4Clearance")
  dimension "d833" distance P1 P5 = 22.6274 (= "abs(mountCircle / ( 2 * sqrt(2) ))")
  dimension "d834" distance P1 P5 = 22.6274 (= "abs(-mountCircle / ( 2 * sqrt(2) ))")
  dimension "d835" diameter C4 = 4.3 (= "m4Clearance")
extrude "Extrude36" cut sketch "B Four Mount Holes" no distance stored
sketch "B M4 Nut Pocket 1" plane through (-0.3536, -0.3536, 0) normal (0.7071, 0.7071, 0) x axis (0, 0, 1)
  line L1 (24.7059, 26.2274) -> (26.7843, 22.6274)
  line L2 (20.549, 26.2274) -> (24.7059, 26.2274)
  line L3 (18.4705, 22.6274) -> (20.549, 26.2274)
  line L4 (20.549, 19.0274) -> (18.4705, 22.6274)
  line L5 (24.7059, 19.0274) -> (20.549, 19.0274)
  line L6 (26.7843, 22.6274) -> (24.7059, 19.0274)
  circle C1 centre (22.6274, 22.6274) radius 4.1569
  point P3 (26.7843, 22.6274)
  point P4 (24.7059, 26.2274)
  point P5 (20.549, 26.2274)
  point P6 (18.4705, 22.6274)
  point P7 (20.549, 19.0274)
  point P8 (24.7059, 19.0274)
  point P1 (0, 0)
  point P2 (22.6274, 22.6274)
  coincident C1 P3
  coincident C1 P4
  coincident C1 P5
  coincident C1 P6
  coincident C1 P7
  coincident C1 P8
  equal L1 L2
  equal L1 L3
  equal L1 L4
  equal L1 L5
  equal L1 L6
  horizontal L2
  dimension "d838" distance P1 P2 = 22.6274 (= "abs(mountCircle / ( 2 * sqrt(2) ))")
  dimension "d839" distance P1 P2 = 22.6274 (= "abs(mountCircle / ( 2 * sqrt(2) ))")
  dimension "d840" diameter C1 = 8.3138 (= "2 * ( nutAF ) / sqrt(3)")
extrude "Extrude37" cut sketch "B M4 Nut Pocket 1" profile of L1 L2 L3 L4 L5 L6 no distance stored
sketch "B M4 Nut Pocket 2" plane through (-0.3536, -0.3536, 0) normal (0.7071, 0.7071, 0) x axis (0, 0, 1)
  line L1 (-20.549, 26.2274) -> (-18.4705, 22.6274)
  line L2 (-24.7059, 26.2274) -> (-20.549, 26.2274)
  line L3 (-26.7843, 22.6274) -> (-24.7059, 26.2274)
  line L4 (-24.7059, 19.0274) -> (-26.7843, 22.6274)
  line L5 (-20.549, 19.0274) -> (-24.7059, 19.0274)
  line L6 (-18.4705, 22.6274) -> (-20.549, 19.0274)
  circle C1 centre (-22.6274, 22.6274) radius 4.1569
  point P3 (-18.4705, 22.6274)
  point P4 (-20.549, 26.2274)
  point P5 (-24.7059, 26.2274)
  point P6 (-26.7843, 22.6274)
  point P7 (-24.7059, 19.0274)
  point P8 (-20.549, 19.0274)
  point P1 (0, 0)
  point P2 (-22.6274, 22.6274)
  coincident C1 P3
  coincident C1 P4
  coincident C1 P5
  coincident C1 P6
  coincident C1 P7
  coincident C1 P8
  equal L1 L2
  equal L1 L3
  equal L1 L4
  equal L1 L5
  equal L1 L6
  horizontal L2
  dimension "d843" distance P1 P2 = 22.6274 (= "abs(-mountCircle / ( 2 * sqrt(2) ))")
  dimension "d844" distance P1 P2 = 22.6274 (= "abs(mountCircle / ( 2 * sqrt(2) ))")
  dimension "d845" diameter C1 = 8.3138 (= "2 * ( nutAF ) / sqrt(3)")
extrude "Extrude38" cut sketch "B M4 Nut Pocket 2" profile of L1 L2 L3 L4 L5 L6 no distance stored
sketch "B M4 Nut Pocket 3" plane through (-0.3536, -0.3536, 0) normal (0.7071, 0.7071, 0) x axis (0, 0, 1)
  line L1 (-20.549, -19.0274) -> (-18.4705, -22.6274)
  line L2 (-24.7059, -19.0274) -> (-20.549, -19.0274)
  line L3 (-26.7843, -22.6274) -> (-24.7059, -19.0274)
  line L4 (-24.7059, -26.2274) -> (-26.7843, -22.6274)
  line L5 (-20.549, -26.2274) -> (-24.7059, -26.2274)
  line L6 (-18.4705, -22.6274) -> (-20.549, -26.2274)
  circle C1 centre (-22.6274, -22.6274) radius 4.1569
  point P3 (-18.4705, -22.6274)
  point P4 (-20.549, -19.0274)
  point P5 (-24.7059, -19.0274)
  point P6 (-26.7843, -22.6274)
  point P7 (-24.7059, -26.2274)
  point P8 (-20.549, -26.2274)
  point P1 (0, 0)
  point P2 (-22.6274, -22.6274)
  coincident C1 P3
  coincident C1 P4
  coincident C1 P5
  coincident C1 P6
  coincident C1 P7
  coincident C1 P8
  equal L1 L2
  equal L1 L3
  equal L1 L4
  equal L1 L5
  equal L1 L6
  horizontal L2
  dimension "d848" distance P1 P2 = 22.6274 (= "abs(-mountCircle / ( 2 * sqrt(2) ))")
  dimension "d849" distance P1 P2 = 22.6274 (= "abs(-mountCircle / ( 2 * sqrt(2) ))")
  dimension "d850" diameter C1 = 8.3138 (= "2 * ( nutAF ) / sqrt(3)")
extrude "Extrude39" cut sketch "B M4 Nut Pocket 3" profile of L1 L2 L3 L4 L5 L6 no distance stored
sketch "B M4 Nut Pocket 4" plane through (-0.3536, -0.3536, 0) normal (0.7071, 0.7071, 0) x axis (0, 0, 1)
  line L1 (24.7059, -19.0274) -> (26.7843, -22.6274)
  line L2 (20.549, -19.0274) -> (24.7059, -19.0274)
  line L3 (18.4705, -22.6274) -> (20.549, -19.0274)
  line L4 (20.549, -26.2274) -> (18.4705, -22.6274)
  line L5 (24.7059, -26.2274) -> (20.549, -26.2274)
  line L6 (26.7843, -22.6274) -> (24.7059, -26.2274)
  circle C1 centre (22.6274, -22.6274) radius 4.1569
  point P3 (26.7843, -22.6274)
  point P4 (24.7059, -19.0274)
  point P5 (20.549, -19.0274)
  point P6 (18.4705, -22.6274)
  point P7 (20.549, -26.2274)
  point P8 (24.7059, -26.2274)
  point P1 (0, 0)
  point P2 (22.6274, -22.6274)
  coincident C1 P3
  coincident C1 P4
  coincident C1 P5
  coincident C1 P6
  coincident C1 P7
  coincident C1 P8
  equal L1 L2
  equal L1 L3
  equal L1 L4
  equal L1 L5
  equal L1 L6
  horizontal L2
  dimension "d853" distance P1 P2 = 22.6274 (= "abs(mountCircle / ( 2 * sqrt(2) ))")
  dimension "d854" distance P1 P2 = 22.6274 (= "abs(-mountCircle / ( 2 * sqrt(2) ))")
  dimension "d855" diameter C1 = 8.3138 (= "2 * ( nutAF ) / sqrt(3)")
extrude "Extrude40" cut sketch "B M4 Nut Pocket 4" profile of L1 L2 L3 L4 L5 L6 no distance stored
sketch "B Hub Service Slots" plane through (0, 0, 0) normal (0, 0, 1) x axis (1, 0, 0)
  line L1 (-30.4056, -12.0208) -> (-14.8492, 3.5355)
  line L2 (-12.0208, -30.4056) -> (-30.4056, -12.0208)
  line L3 (3.5355, -14.8492) -> (-12.0208, -30.4056)
  line L4 (-14.8492, 3.5355) -> (3.5355, -14.8492)
  point P1 (0, 0)
  point P2 (-14.8492, 3.5355)
  point P3 (-30.4056, -12.0208)
  point P4 (-12.0208, -30.4056)
  point P5 (3.5355, -14.8492)
  dimension "d858" distance P1 P2 = 14.8492 (= "abs(( -8 mm - 13 mm ) / sqrt(2))")
  dimension "d859" distance P1 P2 = 3.5355 (= "abs(( -8 mm + 13 mm ) / sqrt(2))")
  dimension "d860" distance P1 P3 = 30.4056 (= "abs(( -30 mm - 13 mm ) / sqrt(2))")
  dimension "d861" distance P1 P3 = 12.0208 (= "abs(( -30 mm + 13 mm ) / sqrt(2))")
  dimension "d862" distance P1 P4 = 12.0208 (= "abs(( -30 mm + 13 mm ) / sqrt(2))")
  dimension "d863" distance P1 P4 = 30.4056 (= "abs(( -30 mm - 13 mm ) / sqrt(2))")
  dimension "d864" distance P1 P5 = 3.5355 (= "abs(( -8 mm + 13 mm ) / sqrt(2))")
  dimension "d865" distance P1 P5 = 14.8492 (= "abs(( -8 mm - 13 mm ) / sqrt(2))")
extrude "Extrude41" cut sketch "B Hub Service Slots" distance 76 (= "mountOD")
chamfer "Chamfer2" distance 0.3 (= "bedRelief")
chamfer "Chamfer3" distance 0.5 (= "tubeCornerChamfer")
chamfer "Chamfer4" sketch "A Facet 135 Triangle 1" distance 0.3 (= "tubeRimChamfer")
work_plane "WorkPlane25" RotateAngle 0 ExtraOffset 0
work_plane "WorkPlane26" AlongDistance 75 (= "bodyWidth / 2") ExtraOffset 0
sketch "A End Cord Port" plane through (0, 0, 75) normal (0, 0, 1) x axis (1, 0, 0)
  line L1 (125, 0) -> (0, 0)
  circle C1 centre (125, 0) radius 2.25
  point P1 (0, 0)
  point P2 (125, 0)
  horizontal L1
  dimension "d875" distance P1 P2 = 125 (= "abs(( 1 ) * ( ( 1 ) * cordStation ) + ( 0 ) * ( 0 mm ))")
  dimension "d876" diameter C1 = 4.5
extrude "Extrude40" cut sketch "A End Cord Port" profile of C1 no distance stored
chamfer "Chamfer5" distance 0.3 (= "bedRelief")
work_plane "WorkPlane27" RotateAngle 180 ExtraOffset 0
work_plane "WorkPlane28" AlongDistance 75 (= "bodyWidth / 2") ExtraOffset 0
sketch "A End Cord Port (1)" plane through (0, 0, -75) normal (0, 0, -1) x axis (-1, 0, 0)
  line L1 (-125, 0) -> (0, 0)
  circle C1 centre (-125, 0) radius 2.25
  point P1 (0, 0)
  point P2 (-125, 0)
  horizontal L1
  dimension "d884" distance P1 P2 = 125 (= "abs(( -1 ) * ( ( 1 ) * cordStation ) + ( 0 ) * ( 0 mm ))")
  dimension "d885" diameter C1 = 4.5
extrude "Extrude41" cut sketch "A End Cord Port (1)" profile of C1 no distance stored
chamfer "Chamfer6" distance 0.3 (= "bedRelief")
chamfer "Chamfer1" distance 0.3 (= "bedRelief")
chamfer "Chamfer2" distance 0.5 (= "tubeCornerChamfer")
chamfer "Chamfer3" sketch "A Facet 135 Triangle 1" distance 0.3 (= "tubeRimChamfer")
work_plane "WorkPlane21" RotateAngle 0 ExtraOffset 0
work_plane "WorkPlane22" AlongDistance 75 (= "bodyWidth / 2") ExtraOffset 0
sketch "B End Cord Port" plane through (0, 0, 75) normal (0, 0, 1) x axis (1, 0, 0)
  line L1 (-125, 0) -> (0, 0)
  circle C1 centre (-125, 0) radius 2.25
  point P1 (0, 0)
  point P2 (-125, 0)
  horizontal L1
  dimension "d896" distance P1 P2 = 125 (= "abs(( 1 ) * ( ( -1 ) * cordStation ) + ( 0 ) * ( 0 mm ))")
  dimension "d897" diameter C1 = 4.5
extrude "Extrude42" cut sketch "B End Cord Port" profile of C1 no distance stored
chamfer "Chamfer4" distance 0.3 (= "bedRelief")
work_plane "WorkPlane23" RotateAngle 180 ExtraOffset 0
work_plane "WorkPlane24" AlongDistance 75 (= "bodyWidth / 2") ExtraOffset 0
sketch "B End Cord Port (1)" plane through (0, 0, -75) normal (0, 0, -1) x axis (-1, 0, 0)
  line L1 (125, 0) -> (0, 0)
  circle C1 centre (125, 0) radius 2.25
  point P1 (0, 0)
  point P2 (125, 0)
  horizontal L1
  dimension "d905" distance P1 P2 = 125 (= "abs(( -1 ) * ( ( -1 ) * cordStation ) + ( 0 ) * ( 0 mm ))")
  dimension "d906" diameter C1 = 4.5
extrude "Extrude43" cut sketch "B End Cord Port (1)" profile of C1 no distance stored
chamfer "Chamfer5" distance 0.3 (= "bedRelief")
work_plane "WorkPlane1" AlongDistance 22.6 (= "qRearBase") ExtraOffset 0
sketch "D Rear Holder Blank sketch" plane through (15.9806, 15.9806, 0) normal (0.7071, 0.7071, 0) x axis (0, 0, 1)
  circle C1 centre (0, 0) radius 22
  dimension "d912" diameter C1 = 44 (= "coreOD")
extrude "Extrude1" new body sketch "D Rear Holder Blank sketch" along normal blind 10.2 (= "shoulder + rearSeatDepth")
work_plane "WorkPlane2" AlongDistance 22.6 (= "qRearBase") ExtraOffset 0
sketch "D Seal Relief sketch" plane through (15.9806, 15.9806, 0) normal (0.7071, 0.7071, 0) x axis (0, 0, 1)
  circle C1 centre (0, 0) radius 9.75
  dimension "d917" diameter C1 = 19.5 (= "raceRelief")
extrude "Extrude2" cut sketch "D Seal Relief sketch" along normal blind 10.2 (= "shoulder + rearSeatDepth")
work_plane "WorkPlane3" AlongDistance 25.6 (= "qRearBearing") ExtraOffset 0
sketch "D Rear Bearing Seat sketch" plane through (18.1019, 18.1019, 0) normal (0.7071, 0.7071, 0) x axis (0, 0, 1)
  circle C1 centre (0, 0) radius 11.1
  dimension "d922" diameter C1 = 22.2 (= "seatDiameter")
extrude "Extrude3" cut sketch "D Rear Bearing Seat sketch" along normal blind 7.2 (= "rearSeatDepth")
work_plane "WorkPlane4" AlongDistance 22.6 (= "qRearBase") ExtraOffset 0
sketch "D Support Bolt seed" plane through (15.9806, 15.9806, 0) normal (0.7071, 0.7071, 0) x axis (0, 0, 1)
  line L1 (17, 0) -> (0, 0)
  circle C1 centre (17, 0) radius 1.65
  point P1 (0, 0)
  point P2 (17, 0)
  horizontal L1
  dimension "d927" distance P1 P2 = 17 (= "supportCircle / 2")
  dimension "d928" diameter C1 = 3.3 (= "m3Clearance")
extrude "Extrude4" cut sketch "D Support Bolt seed" profile of C1 along normal blind 10.2 (= "shoulder + rearSeatDepth")
circular_pattern "C-Pattern1" TotalAngle 360
chamfer "Chamfer1" distance 0.4 (= "entryChamfer")
chamfer "Chamfer2" distance 0.3 (= "bedRelief")
work_plane "WorkPlane1" AlongDistance -2.5 (= "qFront - capThickness") ExtraOffset 0
sketch "C Front Bearing Cap Ring sketch" plane through (-1.7678, -1.7678, 0) normal (0.7071, 0.7071, 0) x axis (0, 0, 1)
  circle C1 centre (0, 0) radius 22
  circle C2 centre (0, 0) radius 9.75
  dimension "d937" diameter C1 = 44 (= "coreOD")
  dimension "d938" diameter C2 = 19.5 (= "raceRelief")
extrude "Extrude1" new body sketch "C Front Bearing Cap Ring sketch" along normal blind 3 (= "capThickness")
work_plane "WorkPlane2" AlongDistance -2.5 (= "qFront - capThickness") ExtraOffset 0
sketch "C Front Bearing Cap Bolt seed" plane through (-1.7678, -1.7678, 0) normal (0.7071, 0.7071, 0) x axis (0, 0, 1)
  line L1 (17, 0) -> (0, 0)
  circle C1 centre (17, 0) radius 1.65
  point P1 (0, 0)
  point P2 (17, 0)
  horizontal L1
  dimension "d943" distance P1 P2 = 17 (= "supportCircle / 2")
  dimension "d944" diameter C1 = 3.3 (= "m3Clearance")
extrude "Extrude2" cut sketch "C Front Bearing Cap Bolt seed" profile of C1 along normal blind 3 (= "capThickness")
circular_pattern "C-Pattern1" TotalAngle 360
chamfer "Chamfer1" distance 0.3 (= "bedRelief")
work_plane "WorkPlane1" AlongDistance 32.8 (= "qRearEnd") ExtraOffset 0
sketch "E Rear Bearing Cap Ring sketch" plane through (23.1931, 23.1931, 0) normal (0.7071, 0.7071, 0) x axis (0, 0, 1)
  circle C1 centre (0, 0) radius 22
  circle C2 centre (0, 0) radius 9.75
  dimension "d952" diameter C1 = 44 (= "coreOD")
  dimension "d953" diameter C2 = 19.5 (= "raceRelief")
extrude "Extrude1" new body sketch "E Rear Bearing Cap Ring sketch" along normal blind 3 (= "capThickness")
work_plane "WorkPlane2" AlongDistance 32.8 (= "qRearEnd") ExtraOffset 0
sketch "E Rear Bearing Cap Bolt seed" plane through (23.1931, 23.1931, 0) normal (0.7071, 0.7071, 0) x axis (0, 0, 1)
  line L1 (17, 0) -> (0, 0)
  circle C1 centre (17, 0) radius 1.65
  point P1 (0, 0)
  point P2 (17, 0)
  horizontal L1
  dimension "d958" distance P1 P2 = 17 (= "supportCircle / 2")
  dimension "d959" diameter C1 = 3.3 (= "m3Clearance")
